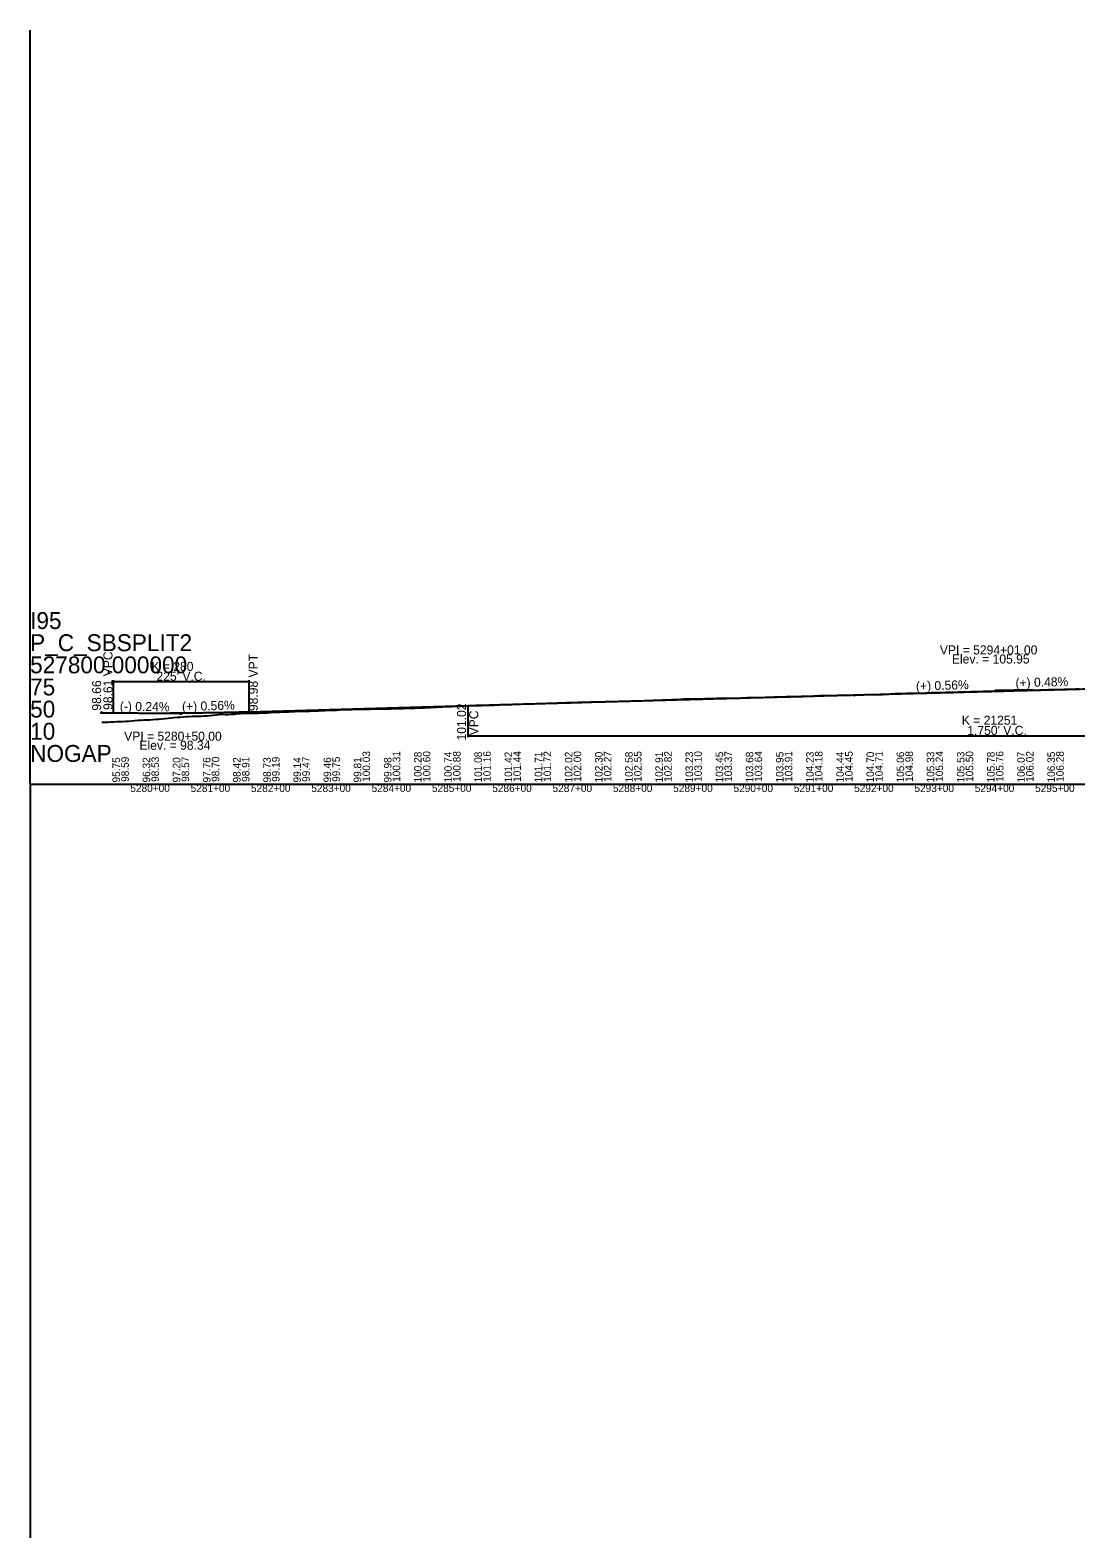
# Model space of a CAD drawing. Extents: x 2121671 to 2169879, y 557274 to 599957.
# Drawn here: x 2157368 to 2159102, y 574937 to 577437 of the extents above; entities that cross this region are included whole.
import ezdxf

# ---------------------------------------------------------------- set-up
doc = ezdxf.new("R2010")
doc.units = 0
for name, color, linetype in [('RD_DDB_GradeTX', 7, 'Continuous'), ('RD_DDB_Profile_EX', 7, 'Continuous'), ('RD_DDB_Profile_Lbl', 7, 'Continuous'), ('RD_DDB_Profile_PR', 7, 'Continuous'), ('RD_DDB_StaTX', 7, 'Continuous'), ('RD_DDB_StripGrade', 7, 'Continuous'), ('RD_DDB_VCLbl', 7, 'Continuous'), ('RD_GPK_Profile_Cell', 7, 'Continuous')]:
    doc.layers.add(name, color=color, linetype=linetype)

msp = doc.modelspace()

# ---------------------------------------------------------------- linework, layer by layer
at = {"layer": 'RD_DDB_GradeTX'}
for p, q in [((2158907, 576339.8), (2158967.9, 576341.5)), ((2159030.9, 576343.1), (2158969.9, 576341.6)), ((2157555.9, 576304.3), (2157616.9, 576303.6)), ((2157679.9, 576305.3), (2157618.9, 576303.6))]:
    msp.add_line(p, q, dxfattribs=at)
for centre in [(2158968.9, 576341.6), (2157486.5, 576305.1), (2157617.9, 576303.6)]:
    msp.add_circle(centre, 1, dxfattribs=at)
at = {"layer": 'RD_DDB_Profile_EX'}
for points in [[(2157986.5, 576312.2), (2157991.5, 576312.4), (2157996.5, 576312.4), (2158001.5, 576312.4), (2158006.5, 576312.7), (2158011.5, 576312.9), (2158016.5, 576313.2), (2158021.5, 576313.4), (2158026.5, 576313.7), (2158031.5, 576313.9), (2158036.5, 576314.1), (2158041.5, 576314.4), (2158046.5, 576314.6), (2158051.5, 576314.8), (2158056.5, 576315.1), (2158061.5, 576315.3), (2158066.5, 576315.5), (2158071.5, 576315.7), (2158076.5, 576315.9), (2158081.5, 576316.1), (2158086.5, 576316.3), (2158091.5, 576316.6), (2158096.5, 576316.8), (2158101.5, 576316.9), (2158106.5, 576317), (2158111.5, 576317.1), (2158116.5, 576317.2), (2158121.5, 576317.3), (2158126.5, 576317.4), (2158131.5, 576317.6), (2158136.5, 576317.8), (2158141.5, 576318), (2158146.5, 576318.2), (2158151.5, 576318.4), (2158156.5, 576318.6), (2158161.5, 576318.7), (2158166.5, 576318.9), (2158171.5, 576319.1), (2158176.5, 576319.2), (2158181.5, 576319.4), (2158186.5, 576319.6), (2158191.5, 576319.8), (2158196.5, 576319.9), (2158201.5, 576320), (2158206.5, 576320.2), (2158211.5, 576320.3), (2158216.5, 576320.4), (2158221.5, 576320.5), (2158226.5, 576320.6), (2158231.5, 576320.8), (2158236.5, 576321), (2158241.5, 576321.2), (2158246.5, 576321.3), (2158251.5, 576321.5), (2158256.5, 576321.7), (2158261.5, 576321.7), (2158266.5, 576321.9), (2158271.5, 576322.1), (2158276.5, 576322.3), (2158281.5, 576322.4), (2158286.5, 576322.5), (2158291.5, 576322.7), (2158296.5, 576322.8), (2158301.5, 576323), (2158306.5, 576323.2), (2158311.5, 576323.3), (2158316.5, 576323.3), (2158321.5, 576323.4), (2158326.5, 576323.5), (2158331.5, 576323.4), (2158336.5, 576323.7), (2158341.5, 576323.9), (2158346.5, 576324), (2158351.5, 576324.2), (2158356.5, 576324.3), (2158361.5, 576324.4), (2158366.5, 576324.7), (2158371.5, 576324.9), (2158376.5, 576325), (2158381.5, 576325), (2158386.5, 576325.1), (2158391.5, 576325.2), (2158396.5, 576325.4), (2158401.5, 576325.8), (2158406.5, 576325.9), (2158411.5, 576326.1), (2158416.5, 576326.3), (2158421.5, 576326.5), (2158426.5, 576326.6), (2158431.5, 576326.7), (2158436.5, 576326.9), (2158441.5, 576327.2), (2158446.5, 576327.5), (2158451.5, 576327.8), (2158456.5, 576327.9), (2158461.5, 576327.9), (2158466.5, 576327.9), (2158471.5, 576328.1), (2158476.5, 576328.2), (2158481.5, 576328.3), (2158486.5, 576328.4)], [(2158486.5, 576328.4), (2158491.5, 576328.5), (2158496.5, 576328.6), (2158501.5, 576328.8), (2158506.5, 576329), (2158511.5, 576329.1), (2158516.5, 576329.1), (2158521.5, 576329.1), (2158526.5, 576329.3), (2158531.5, 576329.3), (2158536.5, 576329.3), (2158541.5, 576329.4), (2158546.5, 576329.6), (2158551.5, 576329.7), (2158556.5, 576330), (2158561.5, 576330.2), (2158566.5, 576330.2), (2158571.5, 576330.3), (2158576.5, 576330.4), (2158581.5, 576330.5), (2158586.5, 576330.6), (2158591.5, 576330.8), (2158596.5, 576331), (2158601.5, 576331.2), (2158606.5, 576331.3), (2158611.5, 576331.4), (2158616.5, 576331.6), (2158621.5, 576331.7), (2158626.5, 576331.8), (2158631.5, 576331.9), (2158636.5, 576332), (2158641.5, 576332.1), (2158646.5, 576332.3), (2158651.5, 576332.5), (2158656.5, 576332.6), (2158661.5, 576332.7), (2158666.5, 576332.9), (2158671.5, 576333.2), (2158676.5, 576333.5), (2158681.5, 576333.8), (2158686.5, 576333.5), (2158691.5, 576333.6), (2158696.5, 576333.7), (2158701.5, 576333.8), (2158706.5, 576333.9), (2158711.5, 576334), (2158716.5, 576333.9), (2158721.5, 576334.3), (2158726.5, 576334.6), (2158731.5, 576334.3), (2158736.5, 576334.2), (2158741.5, 576334.6), (2158746.5, 576334.9), (2158751.5, 576335.1), (2158756.5, 576335.2), (2158761.5, 576335.3), (2158766.5, 576335.3), (2158771.5, 576335.4), (2158776.5, 576335.4), (2158781.5, 576335.5), (2158786.5, 576335.6), (2158791.5, 576335.8), (2158796.5, 576336.5), (2158801.5, 576336.7), (2158806.5, 576336.8), (2158811.5, 576336.9), (2158816.5, 576337.1), (2158821.5, 576337.2), (2158826.5, 576337.4), (2158831.5, 576337.5), (2158836.5, 576337.6), (2158841.5, 576337.6), (2158846.5, 576337.7), (2158851.5, 576337.9), (2158856.5, 576338.1), (2158861.5, 576338.3), (2158866.5, 576338.4), (2158871.5, 576338.6), (2158876.5, 576338.7), (2158881.5, 576338.8), (2158886.5, 576339), (2158891.5, 576339), (2158896.5, 576339.1), (2158901.5, 576339.1), (2158906.5, 576339.3), (2158911.5, 576339.4), (2158916.5, 576339.5), (2158921.5, 576339.5), (2158926.5, 576339.6), (2158931.5, 576339.7), (2158936.5, 576339.9), (2158941.5, 576340.1), (2158946.5, 576340.3), (2158951.5, 576340.3), (2158956.5, 576340.3), (2158961.5, 576340.4), (2158966.5, 576340.7), (2158971.5, 576340.9), (2158976.5, 576341.1), (2158981.5, 576341.3), (2158986.5, 576341.5)], [(2158986.5, 576341.5), (2158991.5, 576341.6), (2158996.5, 576341.7), (2159001.5, 576341.8), (2159006.5, 576341.9), (2159011.5, 576342), (2159016.5, 576342.1), (2159021.5, 576342.2), (2159026.5, 576342.4), (2159031.5, 576342.5), (2159036.5, 576342.6), (2159041.5, 576342.8), (2159046.5, 576343), (2159051.5, 576343.2), (2159056.5, 576343.5), (2159061.5, 576343.6), (2159066.5, 576343.6), (2159071.5, 576343.6), (2159076.5, 576343.7), (2159081.5, 576343.9), (2159086.5, 576344), (2159091.5, 576344.2), (2159096.5, 576344.3), (2159101.5, 576344.4), (2159106.5, 576344.4)], [(2157486.5, 576289.4), (2157491.5, 576289.5), (2157496.5, 576289.4), (2157501.5, 576289.7), (2157506.5, 576290), (2157511.5, 576290.3), (2157516.5, 576290.5), (2157521.5, 576290.7), (2157526.5, 576290.9), (2157531.5, 576291.2), (2157536.5, 576291.6), (2157541.5, 576292.1), (2157546.5, 576292.5), (2157551.5, 576292.7), (2157556.5, 576293.1), (2157561.5, 576293.2), (2157566.5, 576293.4), (2157571.5, 576293.6), (2157576.5, 576294.2), (2157581.5, 576294.5), (2157586.5, 576294.9), (2157591.5, 576295.6), (2157596.5, 576296.2), (2157601.5, 576296.6), (2157606.5, 576297), (2157611.5, 576297.4), (2157616.5, 576297.7), (2157621.5, 576298.1), (2157626.5, 576298.8), (2157631.5, 576299), (2157636.5, 576299.3), (2157641.5, 576299.3), (2157646.5, 576299.4), (2157651.5, 576299.5), (2157656.5, 576299.6), (2157661.5, 576299.8), (2157666.5, 576300.5), (2157671.5, 576301), (2157676.5, 576301.5), (2157681.5, 576302.1), (2157686.5, 576302.6), (2157691.5, 576302.3), (2157696.5, 576302.3), (2157701.5, 576302.4), (2157706.5, 576302.9), (2157711.5, 576303.5), (2157716.5, 576303.9), (2157721.5, 576304.1), (2157726.5, 576304.1), (2157731.5, 576304.2), (2157736.5, 576304.3), (2157741.5, 576304.4), (2157746.5, 576304.5), (2157751.5, 576304.6), (2157756.5, 576304.8), (2157761.5, 576305.1), (2157766.5, 576305.3), (2157771.5, 576305.8), (2157776.5, 576306), (2157781.5, 576306.2), (2157786.5, 576306.4), (2157791.5, 576306.6), (2157796.5, 576306.7), (2157801.5, 576306.9), (2157806.5, 576307.2), (2157811.5, 576307.4), (2157816.5, 576307.5), (2157821.5, 576307.6), (2157826.5, 576307.7), (2157831.5, 576307.7), (2157836.5, 576307.9), (2157841.5, 576308.1), (2157846.5, 576308.4), (2157851.5, 576308.5), (2157856.5, 576308.8), (2157861.5, 576309), (2157866.5, 576309.1), (2157871.5, 576309.3), (2157876.5, 576309.5), (2157881.5, 576309.8), (2157886.5, 576310.1), (2157891.5, 576310.3), (2157896.5, 576310.4), (2157901.5, 576310.6), (2157906.5, 576310.7), (2157911.5, 576310.8), (2157916.5, 576310.9), (2157921.5, 576310.9), (2157926.5, 576311), (2157931.5, 576311.1), (2157936.5, 576311.2), (2157941.5, 576311.4), (2157946.5, 576311.4), (2157951.5, 576311.5), (2157956.5, 576311.6), (2157961.5, 576311.7), (2157966.5, 576311.7), (2157971.5, 576311.8), (2157976.5, 576312), (2157981.5, 576312.1), (2157986.5, 576312.2)]]:
    msp.add_lwpolyline(points, dxfattribs=at)
at = {"layer": 'RD_DDB_Profile_PR'}
for p, q in [((2157486.5, 576305.1), (2157505.4, 576304.9)), ((2157730.4, 576306.7), (2158093.9, 576316.9))]:
    msp.add_line(p, q, dxfattribs=at)
for points in [[(2158093.9, 576316.9), (2158128.9, 576317.9), (2158163.9, 576318.9), (2158198.9, 576319.9), (2158233.9, 576320.9), (2158268.9, 576321.8), (2158303.9, 576322.8), (2158338.9, 576323.8), (2158373.9, 576324.7), (2158408.9, 576325.7), (2158443.9, 576326.7), (2158478.9, 576327.6), (2158513.9, 576328.6), (2158548.9, 576329.5), (2158583.9, 576330.5), (2158618.9, 576331.4), (2158653.9, 576332.3), (2158688.9, 576333.3), (2158723.9, 576334.2), (2158758.9, 576335.1), (2158793.9, 576336.1), (2158828.9, 576337), (2158863.9, 576337.9), (2158898.9, 576338.8), (2158933.9, 576339.8), (2158968.9, 576340.7), (2159003.9, 576341.6), (2159038.9, 576342.5), (2159073.9, 576343.4), (2159108.9, 576344.3), (2159143.9, 576345.2), (2159178.9, 576346.1), (2159213.9, 576347), (2159248.9, 576347.9), (2159283.9, 576348.8), (2159318.9, 576349.7), (2159353.9, 576350.5), (2159388.9, 576351.4), (2159423.9, 576352.3), (2159458.9, 576353.2), (2159493.9, 576354), (2159528.9, 576354.9), (2159563.9, 576355.8), (2159598.9, 576356.6), (2159633.9, 576357.5), (2159668.9, 576358.4), (2159703.9, 576359.2), (2159738.9, 576360.1), (2159773.9, 576360.9), (2159808.9, 576361.8), (2159843.9, 576362.6)], [(2157505.4, 576304.9), (2157509.9, 576304.8), (2157514.4, 576304.8), (2157518.9, 576304.8), (2157523.4, 576304.7), (2157527.9, 576304.7), (2157532.4, 576304.6), (2157536.9, 576304.6), (2157541.4, 576304.6), (2157545.9, 576304.6), (2157550.4, 576304.5), (2157554.9, 576304.5), (2157559.4, 576304.5), (2157563.9, 576304.5), (2157568.4, 576304.5), (2157572.9, 576304.5), (2157577.4, 576304.5), (2157581.9, 576304.5), (2157586.4, 576304.5), (2157590.9, 576304.5), (2157595.4, 576304.5), (2157599.9, 576304.6), (2157604.4, 576304.6), (2157608.9, 576304.6), (2157613.4, 576304.6), (2157617.9, 576304.7), (2157622.4, 576304.7), (2157626.9, 576304.8), (2157631.4, 576304.8), (2157635.9, 576304.9), (2157640.4, 576304.9), (2157644.9, 576305), (2157649.4, 576305), (2157653.9, 576305.1), (2157658.4, 576305.2), (2157662.9, 576305.2), (2157667.4, 576305.3), (2157671.9, 576305.4), (2157676.4, 576305.5), (2157680.9, 576305.5), (2157685.4, 576305.6), (2157689.9, 576305.7), (2157694.4, 576305.8), (2157698.9, 576305.9), (2157703.4, 576306), (2157707.9, 576306.1), (2157712.4, 576306.2), (2157716.9, 576306.4), (2157721.4, 576306.5), (2157725.9, 576306.6), (2157730.4, 576306.7)]]:
    msp.add_spline(points, degree=3, dxfattribs=at)
at = {"layer": 'RD_DDB_VCLbl'}
for p, q in [((2157505.4, 576359.2), (2157505.4, 576304.9)), ((2157505.4, 576356.7), (2157730.4, 576356.7)), ((2157730.4, 576359.2), (2157730.4, 576306.7)), ((2158093.9, 576264.4), (2158093.9, 576316.9)), ((2158093.9, 576266.9), (2159843.9, 576266.9))]:
    msp.add_line(p, q, dxfattribs=at)
at = {"layer": 'RD_GPK_Profile_Cell'}
for q in [(2157367.9, 577436.8), (2160567.9, 576186.8), (2157367.9, 574936.8)]:
    msp.add_line((2157367.9, 576186.8), q, dxfattribs=at)

# ---------------------------------------------------------------- texts
at = {"layer": 'RD_DDB_GradeTX'}
for s, rotation, p in [('(+) 0.56%', 1.6122, (2158836.7, 576341.7)), ('(+) 0.48%', 1.3765, (2159001.7, 576347.2)), ('(+) 0.56%', 1.6122, (2157619.9, 576307.8)), ('(-) 0.24%', 359.3125, (2157516.5, 576308.3))]:
    msp.add_text(s, height=15, rotation=rotation, dxfattribs=at).set_placement(p)
at = {"layer": 'RD_DDB_Profile_Lbl'}
for s, p in [('VPI = 5294+01.00', (2158876.1, 576401.6)), ('Elev. = 105.95', (2158896.1, 576386.6)), ('VPI = 5280+50.00', (2157523.8, 576258.6)), ('Elev. = 98.34', (2157549.1, 576243.6))]:
    msp.add_text(s, height=15, dxfattribs=at).set_placement(p)
msp.add_text('98.66', height=15, rotation=90, dxfattribs=at).set_placement((2157485.6, 576308.5))
at = {"layer": 'RD_DDB_StaTX'}
for s, p in [('5280+00', (2157534, 576173.5)), ('5281+00', (2157634, 576173.5)), ('5282+00', (2157734, 576173.5)), ('5283+00', (2157834, 576173.5)), ('5284+00', (2157934, 576173.5)), ('5285+00', (2158034, 576173.5)), ('5286+00', (2158134, 576173.5)), ('5287+00', (2158234, 576173.5)), ('5288+00', (2158334, 576173.5)), ('5289+00', (2158434, 576173.5)), ('5290+00', (2158534, 576173.5)), ('5291+00', (2158634, 576173.5)), ('5292+00', (2158734, 576173.5)), ('5293+00', (2158834, 576173.5)), ('5294+00', (2158934, 576173.5)), ('5295+00', (2159034, 576173.5))]:
    msp.add_text(s, height=12.5, dxfattribs=at).set_placement(p)
at = {"layer": 'RD_DDB_StripGrade'}
for s, height, p in [('98.61 VPC', 15, (2157504.4, 576309.7)), ('98.98 VPT', 15, (2157745.3, 576307.7)), ('101.02 ', 15, (2158090.6, 576259)), ('VPC', 15, (2158110.8, 576267.5)), ('95.75', 12.5, (2157516.9, 576189.3)), ('98.59', 12.5, (2157531.5, 576190.3)), ('96.32', 12.5, (2157566.9, 576189.3)), ('98.53', 12.5, (2157581.5, 576190.3)), ('97.20', 12.5, (2157616.9, 576189.3)), ('98.57', 12.5, (2157631.5, 576190.3)), ('97.76', 12.5, (2157666.9, 576189.3)), ('98.70', 12.5, (2157681.5, 576190.3)), ('98.42', 12.5, (2157716.9, 576189.3)), ('98.91', 12.5, (2157731.5, 576190.3)), ('98.73', 12.5, (2157766.9, 576189.3)), ('99.19', 12.5, (2157781.5, 576190.3)), ('99.14', 12.5, (2157816.9, 576189.3)), ('99.47', 12.5, (2157831.5, 576190.3)), ('99.46', 12.5, (2157866.9, 576189.3)), ('99.75', 12.5, (2157881.5, 576190.3)), ('99.81', 12.5, (2157916.9, 576189.3)), ('100.03', 12.5, (2157931.5, 576190.3)), ('99.98', 12.5, (2157966.9, 576189.3)), ('100.31', 12.5, (2157981.5, 576190.3)), ('100.28', 12.5, (2158016.9, 576189.3)), ('100.60', 12.5, (2158031.5, 576190.3)), ('100.74', 12.5, (2158066.9, 576189.3)), ('100.88', 12.5, (2158081.5, 576190.3)), ('101.08', 12.5, (2158116.9, 576189.3)), ('101.16', 12.5, (2158131.5, 576190.3)), ('101.42', 12.5, (2158166.9, 576189.3)), ('101.44', 12.5, (2158181.5, 576190.3)), ('101.71', 12.5, (2158216.9, 576189.3)), ('101.72', 12.5, (2158231.5, 576190.3)), ('102.02', 12.5, (2158266.9, 576189.3)), ('102.00', 12.5, (2158281.5, 576190.3)), ('102.30', 12.5, (2158316.9, 576189.3)), ('102.27', 12.5, (2158331.5, 576190.3)), ('102.58', 12.5, (2158366.9, 576189.3)), ('102.55', 12.5, (2158381.5, 576190.3)), ('102.91', 12.5, (2158416.9, 576189.3)), ('102.82', 12.5, (2158431.5, 576190.3)), ('103.23', 12.5, (2158466.9, 576189.3)), ('103.10', 12.5, (2158481.5, 576190.3)), ('103.45', 12.5, (2158516.9, 576189.3)), ('103.37', 12.5, (2158531.5, 576190.3)), ('103.68', 12.5, (2158566.9, 576189.3)), ('103.64', 12.5, (2158581.5, 576190.3)), ('103.95', 12.5, (2158616.9, 576189.3)), ('103.91', 12.5, (2158631.5, 576190.3)), ('104.23', 12.5, (2158666.9, 576189.3)), ('104.18', 12.5, (2158681.5, 576190.3)), ('104.44', 12.5, (2158716.9, 576189.3)), ('104.45', 12.5, (2158731.5, 576190.3)), ('104.70', 12.5, (2158766.9, 576189.3)), ('104.71', 12.5, (2158781.5, 576190.3)), ('105.06', 12.5, (2158816.9, 576189.3)), ('104.98', 12.5, (2158831.5, 576190.3)), ('105.33', 12.5, (2158866.9, 576189.3)), ('105.24', 12.5, (2158881.5, 576190.3)), ('105.53', 12.5, (2158916.9, 576189.3)), ('105.50', 12.5, (2158931.5, 576190.3)), ('105.78', 12.5, (2158966.9, 576189.3)), ('105.76', 12.5, (2158981.5, 576190.3)), ('106.07', 12.5, (2159016.9, 576189.3)), ('106.02', 12.5, (2159031.5, 576190.3)), ('106.35', 12.5, (2159066.9, 576189.3)), ('106.28', 12.5, (2159081.5, 576190.3))]:
    msp.add_text(s, height=height, rotation=90, dxfattribs=at).set_placement(p)
at = {"layer": 'RD_DDB_VCLbl'}
for s, p in [('K = 280', (2157569, 576374.3)), ("225' V.C.", (2157577.4, 576358)), ('K = 21251', (2158912.5, 576285.1)), ("1,750' V.C.", (2158921.6, 576268.2))]:
    msp.add_text(s, height=15, dxfattribs=at).set_placement(p)
at = {"layer": 'RD_GPK_Profile_Cell'}
for s, p in [('I95', (2157367.9, 576443.8)), ('P_C_SBSPLIT2', (2157367.9, 576407.1)), ('527800.000000', (2157367.9, 576370.4)), ('75', (2157367.9, 576333.7)), ('50', (2157367.9, 576297)), ('10', (2157367.9, 576260.3)), ('NOGAP', (2157367.9, 576223.5))]:
    msp.add_text(s, height=28, dxfattribs=at).set_placement(p)

doc.saveas('drawing.dxf')
